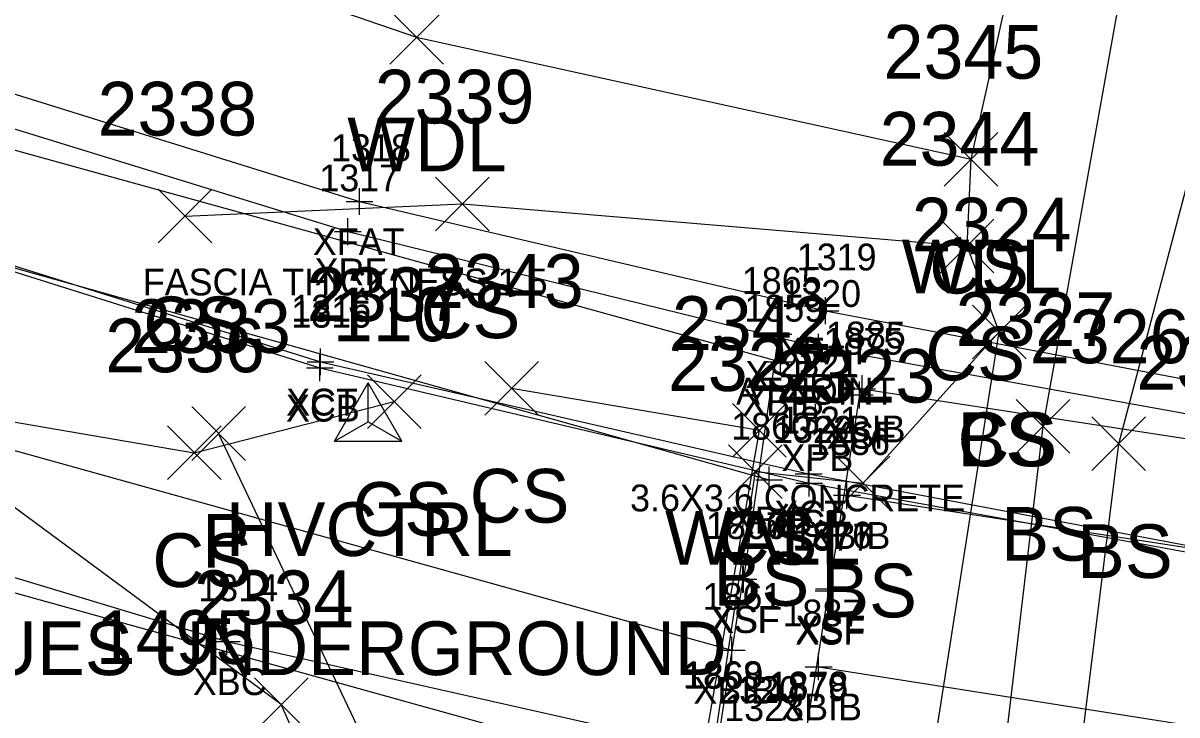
# Model space of a CAD drawing. Extents: x 1761340 to 1763889, y 696770 to 706023.
# Drawn here: x 1761614.72 to 1761657.73, y 700852.76 to 700878.53 of the extents above; entities that cross this region are included whole.
import ezdxf

# ---------------------------------------------------------------- set-up
doc = ezdxf.new("R2010")
doc.units = 0
for name, color, linetype in [('B_A', 7, 'Continuous'), ('B_C', 7, 'Continuous'), ('B_I', 7, 'Continuous'), ('B_TIC', 7, 'Continuous'), ('BB', 7, 'Continuous'), ('BDC', 7, 'Continuous'), ('BDEFAULT', 7, 'Continuous'), ('BELB', 7, 'Continuous'), ('BF', 7, 'Continuous'), ('BR', 7, 'Continuous'), ('C_A', 7, 'Continuous'), ('C_I', 7, 'Continuous'), ('CPSM', 7, 'Continuous'), ('D_A', 7, 'Continuous'), ('D_C', 7, 'Continuous'), ('D_I', 7, 'Continuous'), ('D_TIC', 7, 'Continuous'), ('DCP', 7, 'Continuous'), ('L_A', 7, 'Continuous'), ('L_I', 7, 'Continuous'), ('L_TIC', 7, 'Continuous'), ('LAWA', 7, 'Continuous'), ('LELB', 7, 'Continuous'), ('LW', 7, 'Continuous'), ('R_I', 7, 'Continuous')]:
    doc.layers.add(name, color=color, linetype=linetype)

msp = doc.modelspace()

# ---------------------------------------------------------------- linework, layer by layer
at = {"layer": 'B_TIC'}
for p, q in [((1761627.265, 700871.889), (1761627.341, 700871.889)), ((1761626.83, 700870.765), (1761626.906, 700870.765)), ((1761644.628, 700867.82), (1761644.703, 700867.82)), ((1761642.882, 700866.943), (1761642.957, 700866.943)), ((1761644.371, 700866.459), (1761644.447, 700866.459)), ((1761625.788, 700865.689), (1761625.863, 700865.689)), ((1761625.811, 700865.915), (1761625.886, 700865.915)), ((1761642.959, 700865.912), (1761643.035, 700865.912)), ((1761645.995, 700864.914), (1761646.07, 700864.914)), ((1761645.902, 700864.681), (1761645.978, 700864.681)), ((1761644.255, 700863.843), (1761644.331, 700863.843)), ((1761644.002, 700861.743), (1761644.077, 700861.743)), ((1761642.531, 700861.516), (1761642.607, 700861.516)), ((1761644.024, 700861.397), (1761644.1, 700861.397)), ((1761645.431, 700860.945), (1761645.507, 700860.945)), ((1761641.575, 700857.817), (1761641.65, 700857.817)), ((1761641.549, 700857.814), (1761641.625, 700857.814)), ((1761644.764, 700857.46), (1761644.839, 700857.46)), ((1761644.749, 700857.382), (1761644.825, 700857.382)), ((1761622.315, 700855.499), (1761622.391, 700855.499)), ((1761641.136, 700855.179), (1761641.211, 700855.179)), ((1761644.375, 700854.559), (1761644.45, 700854.559))]:
    msp.add_line(p, q, dxfattribs=at)
for points in [[(1761627.262, 700871.389), (1761627.262, 700872.389)], [(1761626.762, 700871.889), (1761627.762, 700871.889)], [(1761626.827, 700870.265), (1761626.827, 700871.265)], [(1761626.327, 700870.765), (1761627.327, 700870.765)], [(1761644.624, 700867.32), (1761644.624, 700868.32)], [(1761644.124, 700867.82), (1761645.124, 700867.82)], [(1761642.878, 700866.443), (1761642.878, 700867.443)], [(1761642.378, 700866.943), (1761643.378, 700866.943)], [(1761644.368, 700865.959), (1761644.368, 700866.959)], [(1761643.868, 700866.459), (1761644.868, 700866.459)], [(1761625.784, 700865.189), (1761625.784, 700866.189)], [(1761625.807, 700865.415), (1761625.807, 700866.415)], [(1761642.956, 700865.412), (1761642.956, 700866.412)], [(1761625.284, 700865.689), (1761626.284, 700865.689)], [(1761625.307, 700865.915), (1761626.307, 700865.915)], [(1761642.456, 700865.912), (1761643.456, 700865.912)], [(1761645.899, 700864.181), (1761645.899, 700865.181)], [(1761645.991, 700864.414), (1761645.991, 700865.414)], [(1761645.491, 700864.914), (1761646.491, 700864.914)], [(1761644.252, 700863.343), (1761644.252, 700864.343)], [(1761645.399, 700864.681), (1761646.399, 700864.681)], [(1761643.752, 700863.843), (1761644.752, 700863.843)], [(1761643.998, 700861.243), (1761643.998, 700862.243)], [(1761642.528, 700861.016), (1761642.528, 700862.016)], [(1761643.498, 700861.743), (1761644.498, 700861.743)], [(1761644.021, 700860.897), (1761644.021, 700861.897)], [(1761642.028, 700861.516), (1761643.028, 700861.516)], [(1761643.521, 700861.397), (1761644.521, 700861.397)], [(1761645.428, 700860.445), (1761645.428, 700861.445)], [(1761644.928, 700860.945), (1761645.928, 700860.945)], [(1761641.546, 700857.314), (1761641.546, 700858.314)], [(1761641.572, 700857.317), (1761641.572, 700858.317)], [(1761641.072, 700857.817), (1761642.072, 700857.817)], [(1761644.746, 700856.882), (1761644.746, 700857.882)], [(1761644.76, 700856.96), (1761644.76, 700857.96)], [(1761641.046, 700857.814), (1761642.046, 700857.814)], [(1761644.26, 700857.46), (1761645.26, 700857.46)], [(1761644.246, 700857.382), (1761645.246, 700857.382)], [(1761622.312, 700854.999), (1761622.312, 700855.999)], [(1761641.132, 700854.679), (1761641.132, 700855.679)], [(1761621.812, 700855.499), (1761622.812, 700855.499)], [(1761640.632, 700855.179), (1761641.632, 700855.179)], [(1761644.371, 700854.059), (1761644.371, 700855.059)], [(1761643.871, 700854.559), (1761644.871, 700854.559)]]:
    msp.add_lwpolyline(points, dxfattribs=at)
at = {"layer": 'BB'}
for points in [[(1761604.575, 700876.52), (1761642.956, 700865.912)], [(1761603.766, 700872.392), (1761642.528, 700861.516)], [(1761602.715, 700865.868), (1761641.132, 700855.179)], [(1761645.991, 700864.914), (1761684.653, 700858.973)], [(1761645.428, 700860.945), (1761682.879, 700855.189)], [(1761601.935, 700860.779), (1761640.161, 700850.159)], [(1761644.371, 700854.559), (1761682.392, 700848.561)]]:
    msp.add_lwpolyline(points, dxfattribs=at)
at = {"layer": 'BDC'}
for points in [[(1761603.372, 700879.329), (1761602.459, 700873.228), (1761625.807, 700865.915), (1761643.998, 700861.743), (1761666.42, 700857.506), (1761686.349, 700855.322), (1761703.242, 700853.873), (1761720.711, 700853.034), (1761728.973, 700853.355), (1761729.967, 700859.215)], [(1761602.35, 700873.051), (1761625.784, 700865.689), (1761644.021, 700861.397), (1761666.64, 700857.269), (1761686.143, 700854.84), (1761703.209, 700853.454), (1761720.802, 700852.829), (1761729.026, 700852.764)]]:
    msp.add_lwpolyline(points, dxfattribs=at)
at = {"layer": 'BDEFAULT'}
for points in [[(1761642.878, 700866.943), (1761641.572, 700857.817), (1761641.546, 700857.814), (1761640.688, 700852.26), (1761640.717, 700852.234), (1761639.892, 700847.284), (1761639.945, 700847.27), (1761639.021, 700841.723), (1761639.004, 700841.662), (1761638.159, 700836.627)], [(1761645.899, 700864.681), (1761644.76, 700857.46), (1761644.746, 700857.382), (1761643.854, 700851.874), (1761643.826, 700851.779), (1761643.069, 700846.895), (1761643.014, 700846.796), (1761642.178, 700841.346), (1761642.142, 700841.272), (1761641.545, 700837.242)]]:
    msp.add_lwpolyline(points, dxfattribs=at)
at = {"layer": 'BELB'}
msp.add_lwpolyline([(1761601.149, 700861.879), (1761622.312, 700855.499), (1761642.198, 700851.032), (1761664.959, 700846.932), (1761684.404, 700844.626), (1761702.463, 700842.89), (1761719.736, 700841.994), (1761727.361, 700840.892)], dxfattribs=at)
at = {"layer": 'BF'}
msp.add_lwpolyline([(1761603.372, 700879.329), (1761627.262, 700871.889), (1761644.624, 700867.82), (1761667.288, 700863.505), (1761686.862, 700861.108), (1761704.425, 700859.764), (1761721.12, 700859.13), (1761729.967, 700859.215)], dxfattribs=at)
at = {"layer": 'BR'}
msp.add_lwpolyline([(1761603.404, 700877.977), (1761626.827, 700870.765), (1761644.368, 700866.459), (1761666.987, 700862.382), (1761686.603, 700859.803), (1761703.665, 700858.606), (1761720.831, 700858.025), (1761729.539, 700857.943)], dxfattribs=at)
at = {"layer": 'CPSM'}
for p, q in [((1761626.333, 700862.961), (1761627.583, 700865.127)), ((1761628.833, 700862.961), (1761627.583, 700865.127)), ((1761627.583, 700863.683), (1761627.583, 700865.127)), ((1761626.333, 700862.961), (1761627.583, 700863.683)), ((1761627.583, 700863.683), (1761627.583, 700863.683)), ((1761627.583, 700863.683), (1761628.833, 700862.961)), ((1761626.333, 700862.961), (1761628.833, 700862.961))]:
    msp.add_line(p, q, dxfattribs=at)
at = {"layer": 'D_TIC'}
for points in [[(1761621.01, 700862.245), (1761623.01, 700864.245)], [(1761623.01, 700862.245), (1761621.01, 700864.245)]]:
    msp.add_lwpolyline(points, dxfattribs=at)
at = {"layer": 'DCP'}
msp.add_lwpolyline([(1761640.818, 700823.61), (1761622.01, 700863.245)], dxfattribs=at)
at = {"layer": 'L_TIC'}
for points in [[(1761628.386, 700877.008), (1761630.386, 700879.008)], [(1761630.386, 700877.008), (1761628.386, 700879.008)], [(1761649.052, 700872.461), (1761651.052, 700874.461)], [(1761651.052, 700872.461), (1761649.052, 700874.461)], [(1761649.052, 700872.461), (1761651.052, 700874.461)], [(1761651.052, 700872.461), (1761649.052, 700874.461)], [(1761630.096, 700870.796), (1761632.096, 700872.796)], [(1761632.096, 700870.796), (1761630.096, 700872.796)], [(1761619.759, 700870.345), (1761621.759, 700872.345)], [(1761621.759, 700870.345), (1761619.759, 700872.345)], [(1761648.907, 700869.225), (1761650.907, 700871.225)], [(1761650.907, 700869.225), (1761648.907, 700871.225)], [(1761648.907, 700869.225), (1761650.907, 700871.225)], [(1761650.907, 700869.225), (1761648.907, 700871.225)], [(1761650.107, 700866.028), (1761652.107, 700868.028)], [(1761652.107, 700866.028), (1761650.107, 700868.028)], [(1761650.107, 700866.028), (1761652.107, 700868.028)], [(1761652.107, 700866.028), (1761650.107, 700868.028)], [(1761631.927, 700863.926), (1761633.927, 700865.926)], [(1761633.927, 700863.926), (1761631.927, 700865.926)], [(1761627.557, 700863.432), (1761629.557, 700865.432)], [(1761629.557, 700863.432), (1761627.557, 700865.432)], [(1761641.163, 700862.358), (1761643.163, 700864.358)], [(1761643.163, 700862.358), (1761641.163, 700864.358)], [(1761641.163, 700862.358), (1761643.163, 700864.358)], [(1761643.163, 700862.358), (1761641.163, 700864.358)], [(1761651.737, 700862.508), (1761653.737, 700864.508)], [(1761653.737, 700862.508), (1761651.737, 700864.508)], [(1761654.56, 700861.863), (1761656.56, 700863.863)], [(1761656.56, 700861.863), (1761654.56, 700863.863)], [(1761620.099, 700861.527), (1761622.099, 700863.527)], [(1761622.099, 700861.527), (1761620.099, 700863.527)], [(1761641.014, 700860.826), (1761643.014, 700862.826)], [(1761643.014, 700860.826), (1761641.014, 700862.826)], [(1761645.028, 700860.397), (1761647.028, 700862.397)], [(1761647.028, 700860.397), (1761645.028, 700862.397)], [(1761623.344, 700852.144), (1761625.344, 700854.144)], [(1761625.344, 700852.144), (1761623.344, 700854.144)]]:
    msp.add_lwpolyline(points, dxfattribs=at)
at = {"layer": 'LAWA'}
for points in [[(1761629.386, 700878.008), (1761650.052, 700873.461), (1761656.53, 700902.641)], [(1761605.527, 700886.179), (1761629.386, 700878.008)]]:
    msp.add_lwpolyline(points, dxfattribs=at)
at = {"layer": 'LELB'}
for points in [[(1761650.668, 700568.581), (1761653.72, 700589.345), (1761656.228, 700611.846), (1761650.783, 700645.878), (1761646.693, 700682.268), (1761643.965, 700721.139), (1761646.185, 700763.151), (1761649.001, 700791.974), (1761651.08, 700826.684), (1761655.56, 700862.863), (1761665.437, 700900.351), (1761673.527, 700937.717), (1761682.384, 700964.347), (1761693.002, 701008.082), (1761690.127, 701015.338), (1761683.006, 701019.111)], [(1761647.361, 700568.693), (1761651.507, 700589.637), (1761652.179, 700611.172), (1761648.147, 700645.92), (1761644.284, 700683.035), (1761641.556, 700721.375), (1761643.749, 700763.66), (1761644.587, 700792.445), (1761648.472, 700827.402), (1761652.737, 700863.508), (1761659.58, 700901.674), (1761670.104, 700938.531), (1761679.505, 700964.488), (1761691.194, 701008.19), (1761682.174, 701016.504)], [(1761650.212, 700590.246), (1761648.805, 700610.457), (1761644.582, 700645.542), (1761640.712, 700682.502), (1761639.82, 700689.73), (1761639.14, 700693.979), (1761637.85, 700721.718), (1761639.717, 700763.338), (1761641.24, 700792.73), (1761643.277, 700816.475), (1761646.043, 700834.747), (1761651.107, 700867.028), (1761649.907, 700870.225), (1761650.052, 700873.461)], [(1761620.759, 700871.345), (1761631.096, 700871.796), (1761649.907, 700870.225)], [(1761643.963, 700836.697), (1761639.017, 700842.004), (1761642.014, 700861.826), (1761646.028, 700861.397), (1761651.107, 700867.028)], [(1761642.163, 700863.358), (1761632.927, 700864.926)], [(1761639.915, 700830.601), (1761631.782, 700838.831), (1761628.56, 700843.668), (1761624.344, 700853.144), (1761608.772, 700864.631), (1761621.099, 700862.527), (1761628.557, 700864.432)]]:
    msp.add_lwpolyline(points, dxfattribs=at)
at = {"layer": 'LW'}
msp.add_lwpolyline([(1761638.669, 700843.229), (1761642.163, 700863.358)], dxfattribs=at)

# ---------------------------------------------------------------- texts
at = {"layer": 'B_A'}
for s, p in [('XFAT', (1761625.518, 700869.889)), ('XRF', (1761625.587, 700868.765)), ('XFAT', (1761642.88, 700865.82)), ('XSF', (1761641.638, 700864.943)), ('XRF', (1761643.128, 700864.459)), ('XCB', (1761624.52, 700863.689)), ('XCT', (1761624.528, 700863.915)), ('XBIB', (1761641.526, 700863.912)), ('XBIB', (1761644.562, 700862.914)), ('XSF', (1761644.659, 700862.681)), ('XPB', (1761642.988, 700861.843)), ('XBIB', (1761641.099, 700859.516)), ('XCT', (1761642.719, 700859.743)), ('XCB', (1761642.757, 700859.397)), ('XBIB', (1761643.999, 700858.945)), ('XSF', (1761640.305, 700855.814)), ('XSF', (1761640.331, 700855.817)), ('XSF', (1761643.505, 700855.382)), ('XSF', (1761643.52, 700855.46)), ('XBC', (1761621.048, 700853.499)), ('XBIB', (1761639.703, 700853.179)), ('XBIB', (1761642.942, 700852.559))]:
    msp.add_text(s, height=1, dxfattribs=at).set_placement(p)
at = {"layer": 'B_C'}
for s, p in [('FASCIA THICKNESS 1.5', (1761619.183, 700868.389)), ('AT JOINT', (1761641.298, 700864.32)), ('3.6X3.6 CONCRETE', (1761637.346, 700860.343))]:
    msp.add_text(s, height=1, dxfattribs=at).set_placement(p)
at = {"layer": 'B_I'}
for s, p in [('1318', (1761626.199, 700873.389)), ('1317', (1761625.764, 700872.265)), ('1319', (1761643.557, 700869.32)), ('1865', (1761641.508, 700868.443)), ('1320', (1761642.978, 700867.959)), ('1316', (1761624.717, 700867.415)), ('1315', (1761624.721, 700867.189)), ('1859', (1761641.605, 700867.412)), ('1885', (1761644.645, 700866.414)), ('1875', (1761644.553, 700866.181)), ('2321', (1761642.905, 700865.343)), ('1860', (1761641.115, 700863.016)), ('1322', (1761642.675, 700862.897)), ('1321', (1761642.935, 700863.243)), ('1886', (1761644.054, 700862.445)), ('1866', (1761640.174, 700859.317)), ('1867', (1761640.176, 700859.314)), ('1876', (1761643.386, 700858.96)), ('1877', (1761643.399, 700858.882)), ('1314', (1761621.249, 700856.999)), ('1861', (1761640.046, 700856.679)), ('1887', (1761643.025, 700856.059)), ('1868', (1761639.318, 700853.76)), ('1869', (1761639.344, 700853.734)), ('1878', (1761642.507, 700853.374)), ('2320', (1761640.664, 700853.204)), ('1879', (1761642.476, 700853.279)), ('1323', (1761640.852, 700852.532))]:
    msp.add_text(s, height=1, dxfattribs=at).set_placement(p)
at = {"layer": 'C_A'}
msp.add_text('HVCTRL', height=2, dxfattribs=at).set_placement((1761622.276, 700858.683))
at = {"layer": 'C_I'}
msp.add_text('110', height=2, dxfattribs=at).set_placement((1761626.269, 700866.683))
at = {"layer": 'D_A'}
msp.add_text('P', height=2, dxfattribs=at).set_placement((1761621.388, 700858.245))
at = {"layer": 'D_C'}
msp.add_text('CONTINUES UNDERGROUND', height=2, dxfattribs=at).set_placement((1761603.058, 700854.245))
at = {"layer": 'D_I'}
msp.add_text('2333', height=2, dxfattribs=at).set_placement((1761618.751, 700866.245))
at = {"layer": 'L_A'}
for s, p in [('WDL', (1761626.804, 700873.008)), ('WDL', (1761647.469, 700868.461)), ('CS', (1761648.493, 700868.461)), ('CS', (1761629.537, 700866.796)), ('CS', (1761619.2, 700866.345)), ('CS', (1761648.348, 700865.225)), ('CS', (1761648.348, 700865.225)), ('CS', (1761649.548, 700862.028)), ('BS', (1761649.548, 700862.028)), ('CS', (1761631.368, 700859.926)), ('CS', (1761626.998, 700859.432)), ('BS', (1761651.178, 700858.508)), ('WALL', (1761638.651, 700858.358)), ('CS', (1761640.604, 700858.358)), ('CS', (1761619.54, 700857.527)), ('BS', (1761654.001, 700857.863)), ('BS', (1761640.455, 700856.826)), ('BS', (1761644.469, 700856.397))]:
    msp.add_text(s, height=2, dxfattribs=at).set_placement(p)
at = {"layer": 'L_I'}
for s, p in [('2345', (1761646.792, 700876.461)), ('2345', (1761646.792, 700876.461)), ('2339', (1761627.829, 700874.796)), ('2338', (1761617.499, 700874.345)), ('2344', (1761646.647, 700873.225)), ('2344', (1761646.647, 700873.225)), ('2324', (1761647.847, 700870.028)), ('2324', (1761647.847, 700870.028)), ('2343', (1761629.667, 700867.926)), ('2337', (1761625.298, 700867.432)), ('2342', (1761638.903, 700866.358)), ('2342', (1761638.903, 700866.358)), ('2327', (1761649.478, 700866.508)), ('2326', (1761652.246, 700865.863)), ('2336', (1761617.784, 700865.527)), ('2322', (1761638.754, 700864.826)), ('2323', (1761642.768, 700864.397)), ('2334', (1761621.084, 700856.144)), ('1495', (1761617.428, 700854.662))]:
    msp.add_text(s, height=2, dxfattribs=at).set_placement(p)
at = {"layer": 'R_I'}
msp.add_text('2325', height=2, dxfattribs=at).set_placement((1761656.22, 700864.884))

doc.saveas('drawing.dxf')
